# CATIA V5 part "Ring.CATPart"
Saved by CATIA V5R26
Part number: Part1.1
Bounding box of the stored display mesh (mm): x -5 to 5, y -15 to 15, z -15 to 15
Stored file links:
  D:\_Deepak\CATIA\CATIA V5-6R2016_Deepak\Resources\Part files\Partfiles\c12_catia_v5_6r2016_prt\c12_catia_v5-6r2016 figr_12-15\Ring.CATPart
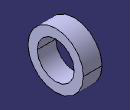
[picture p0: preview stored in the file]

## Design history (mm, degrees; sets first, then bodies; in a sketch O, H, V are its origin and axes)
Body1 (main body)
  Sketch1 on yz-plane, origin (0, 0, 0), H (0, 1, 0), V (0, 0, 1)
    circle A1 centre (0, 0) radius 15
    circle A2 centre (0, 0) radius 10
    radius A1 = 15
    radius A2 = 10
  Pad1: profile Sketch1, direction (1, 0, 0), length 5, mirrored extent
